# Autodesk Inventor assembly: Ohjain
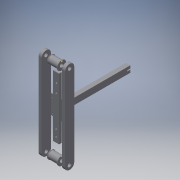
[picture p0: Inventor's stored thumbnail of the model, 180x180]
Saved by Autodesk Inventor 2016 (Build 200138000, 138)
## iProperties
Created: 2016-02
Part Number: Ohjain
Document SubType Name: Assembly
Designer: Juha-Pekka
Author: Juha-Pekka
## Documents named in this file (4)
- C:\Users\Juha-Pekka\Desktop\Assignment2\Ohjain.iam
- C:\Users\Juha-Pekka\Desktop\Assignment2\kisko ja ohjain.iam
- C:\Users\Juha-Pekka\Desktop\Assignment2\side.ipt
- C:\Users\Juha-Pekka\Desktop\Assignment2\pulley.ipt
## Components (5 placed, 3 different names)
1. kisko ja ohjain:1 [sub-assembly]
2. side:1
3. side:2
4. pulley:1
5. pulley:2
